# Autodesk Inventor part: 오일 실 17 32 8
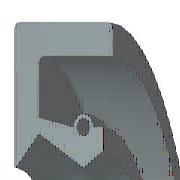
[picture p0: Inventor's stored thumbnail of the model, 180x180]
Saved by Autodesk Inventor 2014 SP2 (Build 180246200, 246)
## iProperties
IsCustomPart: 1
Created: 2012-02
Part Number: 오일 실 17 32 8
Material: 고무
Description: 오일-실
Document SubType Name: Modeling
Standard: KS B 2804
Designer: mduedu
Standards Organization: KS
Language: ko-KR
Size Designation: D - 17 32 8
Categories: <MemberInstance><Categories><Category DisplayName="샤프트 부품" InternalName="7f7aeb1f-a693-4053-b835-cee3144e0d98" Mnemonic="SHFT"><Category DisplayName="실링" Intern
Density: 0.93 g/cm^3
Appearance: 고무 - 검은색 - 버전 1.1
Author: mduedu
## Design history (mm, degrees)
revolve "본체" stored, may be unused: angle "d17" = 90 deg
revolve "스프링1" stored, may be unused: angle "d18" = 90 deg
body "Solid1"
sketch "스케치1"
  geometry: L1 (0, 16)-(8, 16); L2 (8, 14.25)-(1.75, 14.25); L3 (1.75, 10.25)-(4.9, 8.5); L4 (4.9, 8.5)-(0, 8.5); L5 (0, 0)-(9.586, 0) reference; L6 (4.9, 8.5)-(6.3, 9.375); L7 (0, 18)-(0, -3) reference; L8 (-1.941, 0)-(11.507, 0) reference; L9 (4.2, 10.6)-(1.75, 11.21); L10 (1.75, 11.21)-(1.75, 14.25); L11 (0, 16)-(0, 8.588); L12 (4.9, 8.5)-(0, 8.5); L13 (1.75, 10.25)-(0.152, 8.528); L14 (8, 16)-(8, 14.25); L15 (5.6, 10.6)-(6.3, 10.6); L16 (6.3, 10.6)-(6.3, 9.375); C1 r 0.455 at (4.9, 10.6); A1 r 0.7 centre (4.9, 10.6) between (5.6, 10.6) and (4.2, 10.6); A2 r 0.088 centre (0.088, 8.588) between (0, 8.588) and (0.152, 8.528); 1 further point
  constraints: 28 end point, 5 horizontal alignment, 5 point on line, 4 point on circle, 4 vertical alignment, 3 centre point, 3 tangent, 2 collinear, 2 horizontal, 2 perpendicular, 1 coincident, 1 parallel
  dimensions: "d0" = 32 diameter of L1 L5 (= SD2); "d1" = 1.75 distance of L1.end L2.start (= SD); "d2" = 0.91 diameter of C1 (= SPDI); "d3" = 1.4 diameter of A1 (= SPDA); "d4" = 17 diameter of L3.end L5 (= NND); "d5" = 20.5 diameter of L3.start L5 (= TKDM); "d7" = 22.42 diameter of L9.end L5 (= TKDM + 0.24 x SWDT); "d8" = 1.75 distance between parallel lines of L11 L10 (= SD); "d9" = 4.9 distance from line of L11 C1.centre (= SPDST); "d10" = 21.2 diameter of C1.centre L5 (= HLDM); "d11" = 0.0875 radius of A2 (= 0.25 x LAB); "d12" = 6.3 distance between parallel lines of L11 L16 (= SDI); "d13" = 18.75 diameter of L6.end L5 (= ABDM); "d14" = 8 distance from line of L11 L1.end (= SWDT)
fillet "모깎기1" dims "d6" = 0.3 (= RR)
other parameters: "SD2" = 32 [user parameter; used in 1 equation term], "SWDT" = 8 [user parameter; used in 2 equation terms], "RR" = 0.3 [user parameter; used in 1 equation term], "SD" = 1.75 [user parameter; used in 2 equation terms], "NND" = 17 [user parameter; used in 1 equation term], "SPDA" = 1.4 [user parameter; used in 1 equation term], "SPDI" = 0.91 [user parameter; used in 1 equation term], "TKDM" = 20.5 [user parameter; used in 2 equation terms], "HLDM" = 21.2 [user parameter; used in 1 equation term], "ABDM" = 18.75 [user parameter; used in 1 equation term], "SDI" = 6.3 [user parameter; used in 1 equation term], "SPDST" = 4.9 [user parameter; used in 1 equation term], "LAB" = 0.35 [user parameter; used in 1 equation term], "d15" = 0, "d16" = 0, "d19" = 0
